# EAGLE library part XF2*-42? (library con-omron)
OMRON FPC Connector Source : http://www.omron.com/ecb/products/pdf/fpc.pdf
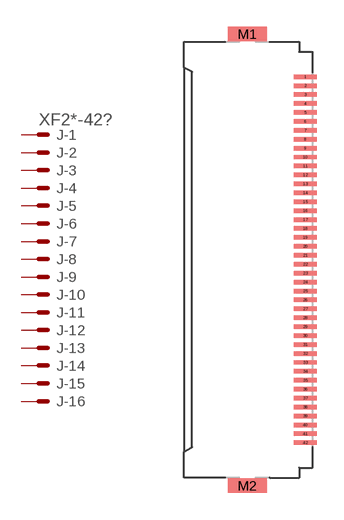
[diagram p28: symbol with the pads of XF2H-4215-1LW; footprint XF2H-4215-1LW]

Designator prefix J; gates -1=PV -2=P -3=P -4=P -5=P -6=P -7=P -8=P -9=P -10=P -11=P -12=P -13=P -14=P -15=P -16=P -17=P -18=P -19=P -20=P -21=P -22=P -23=P -24=P -25=P -26=P -27=P -28=P -29=P -30=P -31=P -32=P -33=P -34=P -35=P -36=P -37=P -38=P -39=P -40=P -41=P -42=P

## XF2H-4215-1LW (OC_FARNELL: unknown; OC_NEWARK: unknown)  [XF2H-4215-1LW]
1  -1:MSV  pas
2  -2:MS  pas
3  -3:MS  pas
4  -4:MS  pas
5  -5:MS  pas
6  -6:MS  pas
7  -7:MS  pas
8  -8:MS  pas
9  -9:MS  pas
10  -10:MS  pas
11  -11:MS  pas
12  -12:MS  pas
13  -13:MS  pas
14  -14:MS  pas
15  -15:MS  pas
16  -16:MS  pas
17  -17:MS  pas
18  -18:MS  pas
19  -19:MS  pas
20  -20:MS  pas
21  -21:MS  pas
22  -22:MS  pas
23  -23:MS  pas
24  -24:MS  pas
25  -25:MS  pas
26  -26:MS  pas
27  -27:MS  pas
28  -28:MS  pas
29  -29:MS  pas
30  -30:MS  pas
31  -31:MS  pas
32  -32:MS  pas
33  -33:MS  pas
34  -34:MS  pas
35  -35:MS  pas
36  -36:MS  pas
37  -37:MS  pas
38  -38:MS  pas
39  -39:MS  pas
40  -40:MS  pas
41  -41:MS  pas
42  -42:MS  pas

## Footprint XF2H-4215-1LW (pad centres in mm)
Standard Rotary Backlock Type (0.5 mm-pitch) Source : http://www.omron.com/ecb/products/pdf/fpc.pdf
smd 1.3 x 0.25: 1 3.175,10.25; 2 3.175,9.75; 3 3.175,9.25; 4 3.175,8.75; 5 3.175,8.25; 6 3.175,7.75; 7 3.175,7.25; 8 3.175,6.75; 9 3.175,6.25; 10 3.175,5.75; 11 3.175,5.25; 12 3.175,4.75; 13 3.175,4.25; 14 3.175,3.75; 15 3.175,3.25; 16 3.175,2.75; 17 3.175,2.25; 18 3.175,1.75; 19 3.175,1.25; 20 3.175,0.75; 21 3.175,0.25; 22 3.175,-0.25; 23 3.175,-0.75; 24 3.175,-1.25; 25 3.175,-1.75; 26 3.175,-2.25; 27 3.175,-2.75; 28 3.175,-3.25; 29 3.175,-3.75; 30 3.175,-4.25; 31 3.175,-4.75; 32 3.175,-5.25; 33 3.175,-5.75; 34 3.175,-6.25; 35 3.175,-6.75; 36 3.175,-7.25; 37 3.175,-7.75; 38 3.175,-8.25; 39 3.175,-8.75; 40 3.175,-9.25; 41 3.175,-9.75; 42 3.175,-10.25
smd 2.2 x 0.8: M1 -0.075,12.65; M2 -0.075,-12.65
